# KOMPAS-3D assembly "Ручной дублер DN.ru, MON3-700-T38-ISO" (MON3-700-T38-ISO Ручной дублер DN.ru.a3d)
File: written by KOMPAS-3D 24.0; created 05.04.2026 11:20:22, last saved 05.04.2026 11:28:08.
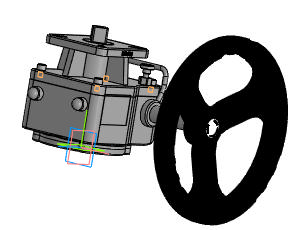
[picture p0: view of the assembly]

Document properties: Автор: R2D2; Полное имя файла: E:\Работа\Зайцев\Аксессуары для пневмоприводов\Ручной дублер DN.ru\MON3-700-T38-ISO Ручной дублер DN.ru\исходные материалы\MON3-700-T38-ISO Ручной дублер DN.ru.a3d

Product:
- Component [detail]: Деталь1  | qty 1  | pos. 1  | Масса: 21.052029; Автор: R2D2; additional columns: Типовые; source file: 3.m3d
- Component [detail]: Деталь1  | qty 1  | pos. 1  | Масса: 21.052029; Автор: R2D2; additional columns: Типовые; source file: 2.m3d
- Component [detail]: Деталь1  | qty 1  | pos. 1  | Масса: 21.052029; Автор: R2D2; additional columns: Типовые; source file: 1.m3d
- Component [detail]: Деталь 2  | qty 1  | pos. 2  | Масса: 6.045553; Автор: R2D2; additional columns: Типовые; source file: Деталь 2 Деталь 2.m3d
- Component [standard]: Hexagon socket head cap screw ISO 4762 - М8 x 12  | qty 4  | Материал: Не определено (density 0 kg/m3); Масса: 0.0109; Раздел спецификации: Стандартные изделия; Рассекать на разрезах: no
- Part/product: Ручной дублер DN.ru  | designation MON3-700-T38-ISO
    Масса: 6.9
    Раздел спецификации: Прочие изделия
    Примечание: D290-00338

Referenced files in E:\Работа\Зайцев\Аксессуары для пневмоприводов\Ручной дублер DN.ru\MON3-700-T38-ISO Ручной дублер DN.ru\исходные материалы\: 3.m3d, 2.m3d, 1.m3d, Деталь 2 Деталь 2.m3d
Referenced files in C:\Program Files\ASCON\KOMPAS-3D v24\Libs\PolynomLib\DATA\vault\Methods\Kompas\3D\: PLib_Screw_DIN_7984_1500.m3d
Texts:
  Hexagon socket head cap screw
  BOSimple***PART:b7fb87e8-e11b-0771-c746-2cb1e6324b0d***SHORTLOC:A259_235BDFABBEFC4171[1,25;12;8;-;Undefined]
  Программные изделия  и базы данных
  MON3-700-T38-ISO
  Деталь1 Деталь1
  Деталь 2 Деталь 2
  Hexagon socket head cap screw ISO 4762 - М8 x 12 (1)
  Hexagon socket head cap screw ISO 4762 - М8 x 12 (2)
  Hexagon socket head cap screw ISO 4762 - М8 x 12 (4)
  Hexagon socket head cap screw ISO 4762 - М8 x 12 (6)
  Ось Y.Начало координат
  Плоскость ZX.Начало координат
  Плоскость XY.Начало координат
  Плоскость ZY.Начало координат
